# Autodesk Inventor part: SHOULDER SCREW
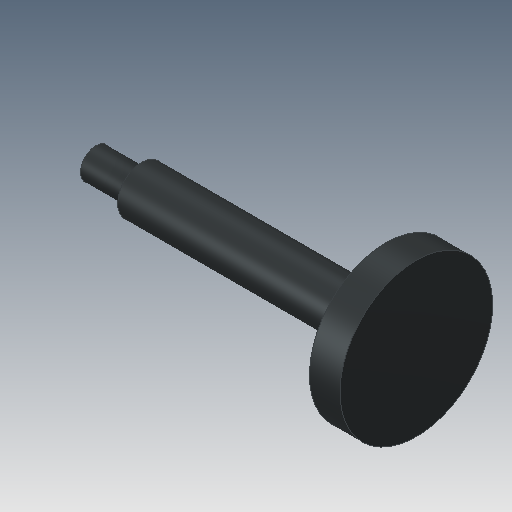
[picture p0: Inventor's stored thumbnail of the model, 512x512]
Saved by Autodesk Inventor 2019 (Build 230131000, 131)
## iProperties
Created: 2016-05
Part Number: SHOULDER SCREW
Material: Iron, Cast
Document SubType Name: Modeling
Designer: CADCIM
Density: 7.15 g/cm^3
Appearance: Iron Gray
Mass: 16.5435 g
Surface Area: 15.8336 cm^2
Volume: 2.31378 cm^3
Author: CADCIM
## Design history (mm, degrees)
sketch "Sketch1"
  geometry: L1 (0, 0)-(0, 2); L2 (0, 2)-(6, 2); L3 (6, 2)-(6, 3.125); L4 (6, 3.125)-(38, 3.125); L5 (38, 3.125)-(38, 10); L6 (38, 10)-(42, 10); L7 (42, 10)-(42, 0); L8 (42, 0)-(0, 0)
  constraints: 16 end point, 7 perpendicular, 1 vertical
  dimensions: "d0" = 4 diameter of L2 L8; "d1" = 6.25 diameter of L4 L8; "d2" = 20 diameter of L6 L8; "d3" = 32 distance between parallel lines of L5 L3; "d4" = 42 distance between parallel lines of L1 L7; "d5" = 4 distance of L5.end L6.end
revolve "Revolution1" sketch "Sketch1" stored, may be unused: angle "d6" = 90 deg
body "Solid1"
